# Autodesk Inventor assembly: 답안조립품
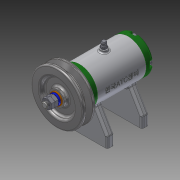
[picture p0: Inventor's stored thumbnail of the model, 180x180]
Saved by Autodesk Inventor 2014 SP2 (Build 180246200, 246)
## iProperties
Created: 2018-05
Part Number: 답안조립품
Document SubType Name: Assembly
Designer: 거성
Author: 거성
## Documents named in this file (16)
- C:\Users\거성\Desktop\480508V1002\답안조립품.iam
- C:\Users\거성\Desktop\480508V1002\본체.ipt
- C:\Users\거성\Desktop\480508V1002\V벨트풀리.ipt
- C:\Users\거성\Desktop\480508V1002\너트 M8.ipt
- C:\Users\거성\Desktop\480508V1002\니플 M6x0.75.ipt
- C:\Users\거성\Desktop\480508V1002\뒤커버.ipt
- C:\Users\거성\Desktop\480508V1002\베어링 6002.ipt
- C:\Users\거성\Desktop\480508V1002\볼트 M4x12.ipt
- C:\Users\거성\Desktop\480508V1002\볼트 M6x8.ipt
- C:\Users\거성\Desktop\480508V1002\스프링와셔 8.ipt
- C:\Users\거성\Desktop\480508V1002\앞커버.ipt
- C:\Users\거성\Desktop\480508V1002\오일 실 15 25 7.ipt
- C:\Users\거성\Desktop\480508V1002\와셔 6x11.5.ipt
- C:\Users\거성\Desktop\480508V1002\와셔 8x17.ipt
- C:\Users\거성\Desktop\480508V1002\축.ipt
- C:\Users\거성\Desktop\480508V1002\키 3x3x12.ipt
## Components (1 placed, 1 different names)
1. V벨트풀리:1 — 각도:2
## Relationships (1: Angle 1)
- 각도:2 [Angle]: V벨트풀리:1
